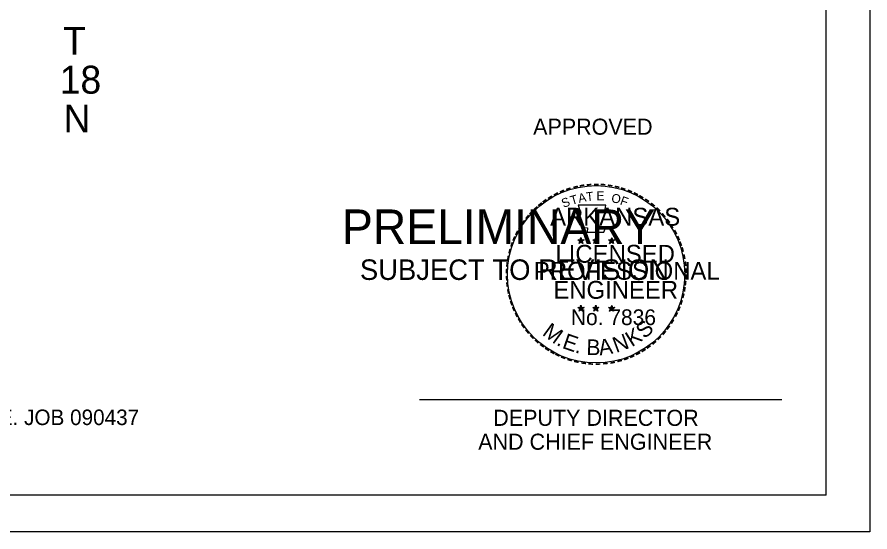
# Model space of a CAD drawing. Extents: x 19118 to 454486, y 1325406 to 1693506.
# Drawn here: x 26165 to 27093, y 1325406 to 1325966 of the extents above; entities that cross this region are included whole.
import ezdxf

# ---------------------------------------------------------------- set-up
doc = ezdxf.new("R2010")
doc.units = 0
for name, color, linetype in [('S_CURB', 7, 'Continuous'), ('S_EDGE_CONCRETE', 7, 'Continuous'), ('S_EDGE_PAVEMENT', 7, 'Continuous'), ('S_SHOULDER', 7, 'Continuous'), ('S_SIGN', 7, 'Continuous')]:
    doc.layers.add(name, color=color, linetype=linetype)

msp = doc.modelspace()

# ---------------------------------------------------------------- linework, layer by layer
at = {"layer": 'S_EDGE_CONCRETE'}
for p, q in [((26775.25, 1325723.58), (26778.65, 1325722.48)), ((26775.25, 1325723.58), (26777.75, 1325723.18)), ((26775.25, 1325723.58), (26777.55, 1325722.38)), ((26776.55, 1325719.58), (26778.65, 1325722.48)), ((26776.55, 1325719.58), (26777.75, 1325721.98)), ((26776.55, 1325719.58), (26778.55, 1325721.68)), ((26778.65, 1325726.08), (26778.25, 1325723.58)), ((26780.75, 1325719.58), (26778.55, 1325721.68)), ((26778.65, 1325722.48), (26778.65, 1325726.08)), ((26778.65, 1325726.08), (26779.15, 1325723.68)), ((26781.95, 1325723.58), (26778.65, 1325722.48)), ((26780.75, 1325719.58), (26778.65, 1325722.48)), ((26781.95, 1325723.58), (26779.25, 1325723.08)), ((26780.75, 1325719.58), (26779.35, 1325722.38)), ((26781.95, 1325723.58), (26780.05, 1325722.58)), ((26791.55, 1325723.58), (26794.95, 1325722.48)), ((26791.55, 1325723.58), (26793.95, 1325723.18)), ((26791.55, 1325723.58), (26793.75, 1325722.38)), ((26792.75, 1325719.58), (26794.95, 1325722.48)), ((26792.75, 1325719.58), (26794.05, 1325721.98)), ((26792.75, 1325719.58), (26794.85, 1325721.68)), ((26794.95, 1325726.08), (26794.55, 1325723.58)), ((26796.95, 1325719.58), (26794.85, 1325721.68)), ((26794.95, 1325722.48), (26794.95, 1325726.08)), ((26794.95, 1325726.08), (26795.35, 1325723.68)), ((26798.25, 1325723.58), (26794.95, 1325722.48)), ((26796.95, 1325719.58), (26794.95, 1325722.48)), ((26798.25, 1325723.58), (26795.45, 1325723.08)), ((26796.95, 1325719.58), (26795.55, 1325722.38)), ((26798.25, 1325723.58), (26796.25, 1325722.58)), ((26808.65, 1325723.48), (26812.05, 1325722.38)), ((26808.65, 1325723.48), (26811.05, 1325722.98)), ((26808.65, 1325723.48), (26810.95, 1325722.28)), ((26809.85, 1325719.48), (26812.05, 1325722.38)), ((26809.85, 1325719.48), (26811.15, 1325721.88)), ((26809.85, 1325719.48), (26812.05, 1325721.58)), ((26812.05, 1325725.88), (26811.65, 1325723.48)), ((26812.05, 1325722.38), (26812.05, 1325725.88)), ((26812.05, 1325725.88), (26812.45, 1325723.48)), ((26815.45, 1325723.48), (26812.05, 1325722.38)), ((26814.05, 1325719.48), (26812.05, 1325722.38)), ((26814.05, 1325719.48), (26812.05, 1325721.58)), ((26815.45, 1325723.48), (26812.55, 1325722.98)), ((26814.05, 1325719.48), (26812.75, 1325722.28)), ((26815.45, 1325723.48), (26813.35, 1325722.48)), ((26775.15, 1325649.98), (26778.55, 1325648.88)), ((26775.15, 1325649.98), (26777.75, 1325649.48)), ((26775.15, 1325649.98), (26777.55, 1325648.78)), ((26776.55, 1325645.98), (26778.55, 1325648.88)), ((26776.55, 1325645.98), (26777.75, 1325648.38)), ((26776.55, 1325645.98), (26778.55, 1325648.18)), ((26778.55, 1325652.38), (26778.15, 1325649.98)), ((26778.55, 1325648.88), (26778.55, 1325652.38)), ((26778.55, 1325652.38), (26779.05, 1325649.98)), ((26781.95, 1325649.98), (26778.55, 1325648.88)), ((26780.75, 1325645.98), (26778.55, 1325648.88)), ((26780.75, 1325645.98), (26778.55, 1325648.08)), ((26781.95, 1325649.98), (26779.15, 1325649.48)), ((26780.75, 1325645.98), (26779.35, 1325648.78)), ((26781.95, 1325649.98), (26780.05, 1325648.98)), ((26791.45, 1325649.98), (26794.85, 1325648.88)), ((26791.45, 1325649.98), (26793.95, 1325649.48)), ((26791.45, 1325649.98), (26793.75, 1325648.78)), ((26792.75, 1325645.98), (26794.85, 1325648.88)), ((26792.75, 1325645.98), (26793.95, 1325648.38)), ((26792.75, 1325645.98), (26794.85, 1325648.18)), ((26794.85, 1325652.38), (26794.45, 1325649.98)), ((26794.85, 1325648.88), (26794.85, 1325652.38)), ((26794.85, 1325652.38), (26795.25, 1325649.98)), ((26798.25, 1325649.98), (26794.85, 1325648.88)), ((26796.85, 1325645.98), (26794.85, 1325648.88)), ((26796.85, 1325645.98), (26794.85, 1325648.08)), ((26798.25, 1325649.98), (26795.35, 1325649.48)), ((26796.85, 1325645.98), (26795.55, 1325648.78)), ((26798.25, 1325649.98), (26796.15, 1325648.98)), ((26808.65, 1325649.88), (26812.05, 1325648.78)), ((26808.65, 1325649.88), (26811.05, 1325649.38)), ((26808.65, 1325649.88), (26810.95, 1325648.68)), ((26809.85, 1325645.88), (26812.05, 1325648.78)), ((26809.85, 1325645.88), (26811.15, 1325648.28)), ((26809.85, 1325645.88), (26812.05, 1325648.08)), ((26812.05, 1325652.28), (26811.65, 1325649.88)), ((26812.05, 1325648.78), (26812.05, 1325652.28)), ((26812.05, 1325652.28), (26812.45, 1325649.88)), ((26815.45, 1325649.88), (26812.05, 1325648.78)), ((26814.05, 1325645.88), (26812.05, 1325648.78)), ((26814.05, 1325645.88), (26812.05, 1325647.98)), ((26815.45, 1325649.88), (26812.55, 1325649.38)), ((26814.05, 1325645.88), (26812.65, 1325648.68)), ((26815.45, 1325649.88), (26813.35, 1325648.88)), ((26602.93, 1325550.01), (26997.29, 1325550.01))]:
    msp.add_line(p, q, dxfattribs=at)
for points in [[(26775.65, 1325761.28), (26778.25, 1325753.18)], [(26809.75, 1325752.38), (26811.15, 1325755.08), (26804.55, 1325754.88), (26805.85, 1325761.28), (26775.65, 1325761.28)], [(26780.45, 1325737.78), (26780.45, 1325736.88), (26785.85, 1325736.68), (26785.35, 1325732.08), (26803.55, 1325732.08), (26805.55, 1325737.28)], [(26778.65, 1325726.08), (26780.75, 1325719.58), (26775.25, 1325723.58), (26781.95, 1325723.58), (26776.55, 1325719.58), (26778.65, 1325726.08)], [(26794.95, 1325726.08), (26796.95, 1325719.58), (26791.55, 1325723.58), (26798.25, 1325723.58), (26792.75, 1325719.58), (26794.95, 1325726.08)], [(26812.05, 1325725.88), (26814.05, 1325719.48), (26808.65, 1325723.48), (26815.45, 1325723.48), (26809.85, 1325719.48), (26812.05, 1325725.88)], [(26778.55, 1325652.38), (26780.75, 1325645.98), (26775.15, 1325649.98), (26781.95, 1325649.98), (26776.55, 1325645.98), (26778.55, 1325652.38)], [(26794.85, 1325652.38), (26796.85, 1325645.98), (26791.45, 1325649.98), (26798.25, 1325649.98), (26792.75, 1325645.98), (26794.85, 1325652.38)], [(26812.05, 1325652.28), (26814.05, 1325645.88), (26808.65, 1325649.88), (26815.45, 1325649.88), (26809.85, 1325645.88), (26812.05, 1325652.28)]]:
    msp.add_lwpolyline(points, dxfattribs=at)
for centre, radius in [((26795.08, 1325686.09), 96.45), ((26778.56, 1325722.47), 1.67), ((26778.56, 1325722.47), 1.41), ((26778.56, 1325722.47), 1.13), ((26778.56, 1325722.47), 0.963), ((26778.56, 1325722.47), 0.726), ((26778.56, 1325722.47), 0.482), ((26778.56, 1325722.47), 0.288), ((26794.79, 1325722.47), 1.67), ((26794.79, 1325722.47), 1.41), ((26794.79, 1325722.47), 1.13), ((26794.79, 1325722.47), 0.963), ((26794.79, 1325722.47), 0.726), ((26794.79, 1325722.47), 0.482), ((26794.79, 1325722.47), 0.288), ((26811.94, 1325722.35), 1.67), ((26811.94, 1325722.35), 1.41), ((26811.94, 1325722.35), 1.13), ((26811.94, 1325722.35), 0.963), ((26811.94, 1325722.35), 0.726), ((26811.94, 1325722.35), 0.482), ((26811.94, 1325722.35), 0.288), ((26778.52, 1325648.86), 1.67), ((26778.52, 1325648.86), 1.41), ((26778.52, 1325648.86), 1.13), ((26778.52, 1325648.86), 0.963), ((26778.52, 1325648.86), 0.726), ((26778.52, 1325648.86), 0.482), ((26778.52, 1325648.86), 0.288), ((26794.74, 1325648.86), 1.67), ((26794.74, 1325648.86), 1.41), ((26794.74, 1325648.86), 1.13), ((26794.74, 1325648.86), 0.963), ((26794.74, 1325648.86), 0.726), ((26794.74, 1325648.86), 0.482), ((26794.74, 1325648.86), 0.288), ((26811.92, 1325648.76), 1.67), ((26811.92, 1325648.76), 1.41), ((26811.92, 1325648.76), 1.13), ((26811.92, 1325648.76), 0.963), ((26811.92, 1325648.76), 0.726), ((26811.92, 1325648.76), 0.482), ((26811.92, 1325648.76), 0.288)]:
    msp.add_circle(centre, radius, dxfattribs=at)
at = {"layer": 'S_EDGE_PAVEMENT'}
msp.add_lwpolyline([(23759.74, 1327539.29), (27093.14, 1327539.29), (27093.14, 1325405.92), (23759.74, 1325405.92)], close=True, dxfattribs=at)
at = {"layer": 'S_SHOULDER'}
for q in [(27045.61, 1327500.35), (23883.81, 1325445.75)]:
    msp.add_line((27045.61, 1325445.75), q, dxfattribs=at)

# ---------------------------------------------------------------- texts
at = {"layer": 'S_CURB'}
for s, height, p in [('T', 30.36, (26215.01, 1325924.79)), ('18', 30.36, (26211.31, 1325882.57)), ('N', 30.36, (26215.49, 1325840.35)), ('P.E. JOB 090437', 16.8484, (26123.68, 1325522.14))]:
    msp.add_text(s, height=height, dxfattribs=at).set_placement(p)
at = {"layer": 'S_EDGE_CONCRETE'}
for s, height, p in [('APPROVED', 17.496, (26726.55, 1325837.88)), ('ARKANSAS', 19.44, (26745.05, 1325738.98)), ('LICENSED', 19.44, (26750.85, 1325698.68)), ('PROFESSIONAL', 19.44, (26727.35, 1325680.18)), ('ENGINEER', 19.44, (26748.55, 1325659.48)), ('No. 7836', 17.078, (26767.61, 1325630.88)), ('DEPUTY DIRECTOR', 17.496, (26683.17, 1325521.28)), ('AND CHIEF ENGINEER', 17.496, (26666.78, 1325495.28))]:
    msp.add_text(s, height=height, dxfattribs=at).set_placement(p)
for s, height, rotation, p in [('-', 15.55, 13.63015, (26770.85, 1325774.58)), ('-', 15.55, 10.21935, (26777.35, 1325776.18)), ('-', 15.55, 5.89682, (26784.45, 1325777.18)), ('-', 15.55, 0.18623, (26791.95, 1325777.88)), ('-', 15.55, 357.74304, (26798.95, 1325777.78)), ('-', 15.55, 352.16173, (26806.15, 1325777.18)), ('-', 15.55, 347.20489, (26813.15, 1325776.18)), ('-', 15.55, 28.79182, (26751.15, 1325766.58)), ('-', 15.55, 24.30721, (26757.25, 1325769.68)), ('-', 15.55, 19.17608, (26763.55, 1325772.28)), ('A', 9.72, 11.21318, (26776.55, 1325763.78)), ('T', 9.72, 6.02276, (26784.75, 1325765.48)), ('E', 9.72, 0.83234, (26795.55, 1325766.58)), ('O', 9.72, 350.4515, (26811.15, 1325764.48)), ('-', 15.55, 342.3362, (26819.45, 1325774.58)), ('-', 15.55, 337.85509, (26826.45, 1325772.48)), ('-', 15.55, 334.12109, (26832.65, 1325769.88)), ('-', 15.55, 38.95066, (26735.15, 1325755.48)), ('-', 15.55, 36.23174, (26739.65, 1325759.18)), ('-', 15.55, 34.06357, (26745.35, 1325762.98)), ('S', 9.72, 21.59401, (26759.65, 1325758.18)), ('T', 9.72, 16.4036, (26768.55, 1325761.38)), ('F', 9.72, 340.07066, (26820.45, 1325762.28)), ('-', 15.55, 329.64089, (26838.25, 1325767.08)), ('-', 15.55, 325.86266, (26844.45, 1325763.58)), ('-', 15.55, 320.52971, (26850.45, 1325759.48)), ('-', 15.55, 48.42305, (26726.55, 1325746.68)), ('-', 15.55, 42.96224, (26730.95, 1325751.38)), ('-', 15.55, 315.57859, (26856.25, 1325754.68)), ('-', 15.55, 54.23247, (26718.65, 1325736.48)), ('-', 15.55, 50.61417, (26722.55, 1325742.08)), ('-', 15.55, 309.87973, (26861.75, 1325749.28)), ('-', 15.55, 306.65218, (26866.95, 1325743.48)), ('-', 15.55, 58.07063, (26715.45, 1325731.38)), ('-', 13.61, 303.67529, (26871.55, 1325737.98)), ('-', 15.55, 67.77427, (26709.85, 1325719.48)), ('-', 15.55, 62.87135, (26712.35, 1325725.38)), ('-', 15.55, 299.66835, (26874.75, 1325731.98)), ('-', 15.55, 294.66279, (26877.95, 1325726.08)), ('-', 15.55, 72.39447, (26707.85, 1325713.38)), ('-', 15.55, 290.57283, (26880.35, 1325720.58)), ('-', 15.55, 75.46096, (26705.85, 1325706.38)), ('-', 15.55, 285.12326, (26882.65, 1325714.88)), ('-', 15.55, 85.18634, (26703.85, 1325692.78)), ('-', 15.55, 81.20126, (26704.65, 1325699.48)), ('-', 15.55, 280.54934, (26884.65, 1325707.58)), ('-', 15.55, 276.59616, (26886.15, 1325700.28)), ('-', 15.55, 89.06224, (26703.65, 1325685.98)), ('-', 15.55, 274.33011, (26886.75, 1325693.18)), ('-', 15.55, 94.19588, (26703.95, 1325678.88)), ('-', 15.55, 269.94067, (26887.05, 1325686.98)), ('-', 15.55, 98.94793, (26704.65, 1325672.48)), ('-', 15.55, 260.99529, (26886.15, 1325674.18)), ('-', 15.55, 263.5172, (26886.85, 1325680.58)), ('-', 15.55, 101.71495, (26705.95, 1325665.28)), ('-', 15.55, 105.45785, (26707.55, 1325659.48)), ('-', 15.55, 255.7626, (26885.15, 1325667.58)), ('-', 15.55, 109.08742, (26709.55, 1325653.38)), ('-', 15.55, 252.86809, (26883.35, 1325660.58)), ('-', 15.55, 114.06432, (26712.05, 1325647.58)), ('-', 15.55, 115.72885, (26715.05, 1325641.58)), ('-', 15.55, 244.61971, (26878.65, 1325647.98)), ('-', 15.55, 247.88866, (26881.25, 1325654.08)), ('-', 15.55, 120.44712, (26718.55, 1325635.88)), ('S', 17.08, 42.9205, (26847.96, 1325615.22)), ('-', 15.55, 239.07125, (26874.85, 1325640.68)), ('-', 15.55, 125.89344, (26722.35, 1325630.48)), ('-', 15.55, 130.71812, (26726.95, 1325624.98)), ('M', 17.08, 323.9056, (26735.58, 1325620.68)), ('K', 17.08, 32.2382, (26833.91, 1325606.65)), ('-', 15.55, 231.25377, (26866.75, 1325628.78)), ('-', 15.55, 233.84524, (26870.95, 1325634.38)), ('-', 15.55, 134.22381, (26731.95, 1325619.78)), ('E', 17.08, 340.88815, (26757.29, 1325606.15)), ('A', 17.08, 8.77022, (26799.06, 1325597.76)), ('N', 17.08, 20.50421, (26816.94, 1325600.41)), ('-', 15.55, 225.76533, (26862.05, 1325623.38)), ('-', 15.55, 138.93382, (26737.05, 1325615.28)), ('-', 15.55, 144.64634, (26742.45, 1325611.28)), ('-', 15.55, 148.08978, (26747.85, 1325607.68)), ('.', 17.08, 336.34072, (26751.07, 1325609.4)), ('B', 17.08, 359.31489, (26784.49, 1325598.3)), ('-', 15.55, 215.73633, (26851.65, 1325613.88)), ('-', 15.55, 221.08509, (26857.05, 1325618.38)), ('-', 15.55, 151.57039, (26753.45, 1325604.48)), ('-', 15.55, 154.60019, (26758.65, 1325602.18)), ('-', 15.55, 158.56121, (26764.65, 1325599.68)), ('.', 17.08, 350.69404, (26771.45, 1325600.88)), ('-', 15.55, 204.25161, (26835.05, 1325603.48)), ('-', 15.55, 207.35684, (26841.05, 1325606.68)), ('-', 15.55, 212.24909, (26846.55, 1325610.08)), ('-', 15.55, 162.79826, (26771.35, 1325597.58)), ('-', 15.55, 167.55551, (26778.25, 1325596.08)), ('-', 15.55, 173.11546, (26785.75, 1325594.98)), ('-', 15.55, 176.51827, (26793.05, 1325594.38)), ('-', 15.55, 181.59176, (26800.35, 1325594.58)), ('-', 15.55, 185.81666, (26808.15, 1325595.38)), ('-', 15.55, 191.28576, (26815.35, 1325596.58)), ('-', 15.55, 195.47429, (26822.45, 1325598.58)), ('-', 15.55, 200.71842, (26829.05, 1325600.88))]:
    msp.add_text(s, height=height, rotation=rotation, dxfattribs=at).set_placement(p)
at = {"layer": 'S_SIGN'}
for s, height, p in [('PRELIMINARY', 37.625, (26518.58, 1325718.99)), ('SUBJECT TO REVISION', 22.3075, (26538.03, 1325679.98))]:
    msp.add_text(s, height=height, dxfattribs=at).set_placement(p)

doc.saveas('drawing.dxf')
